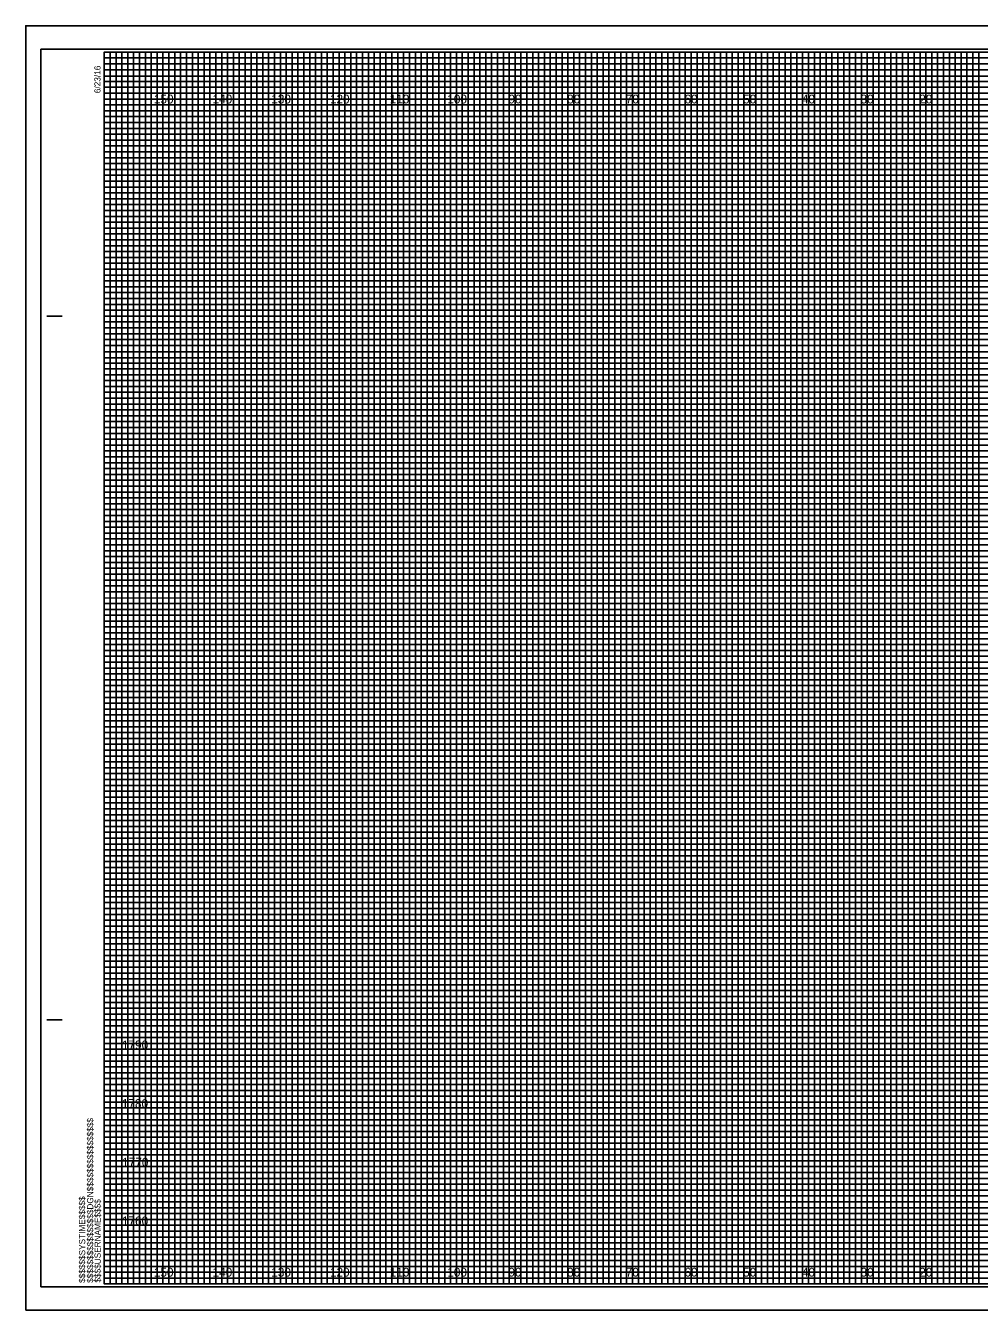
# Model space of a CAD drawing. Extents: x 791 to 1128, y -18 to 860.
# Drawn here: x 791.1 to 953.6, y 640.8 to 859.8 of the extents above; entities that cross this region are included whole.
import ezdxf

# ---------------------------------------------------------------- set-up
doc = ezdxf.new("R2010")
doc.units = 0
for name, color, linetype in [('Prop XS DDE', 7, 'Continuous'), ('Prop XS Earthwork Shape', 7, 'Continuous'), ('Raster_Level_0', 7, 'Continuous'), ('Scratch_Level_1', 7, 'Continuous'), ('Scratch_Level_3', 7, 'Continuous'), ('Sheet Cross Section CELL', 7, 'Continuous'), ('Sheet Cross Section Grid Minor 2 CELL', 7, 'Continuous'), ('Sheet Cutting Line CELL', 7, 'Continuous'), ('Sheet DOT Grid CELL', 7, 'Continuous'), ('Sheet Plot Border Inside CELL', 7, 'Continuous'), ('Sheet Plot Border Outside CELL', 7, 'Continuous')]:
    doc.layers.add(name, color=color, linetype=linetype)

msp = doc.modelspace()

# ---------------------------------------------------------------- linework, layer by layer
at = {"layer": 'Prop XS DDE'}
for p, q in [((804.53, 854.25), (1064.53, 854.25)), ((1064.53, 853.23), (804.53, 853.23)), ((804.53, 853.23), (804.53, 852.25)), ((804.53, 852.25), (1064.53, 852.25)), ((1064.53, 851.14), (804.53, 851.14)), ((804.53, 851.14), (804.53, 849.25)), ((804.53, 849.25), (1124.53, 849.25))]:
    msp.add_line(p, q, dxfattribs=at)
for points in [[(804.53, 848.25), (1074.53, 848.25), (1124.53, 848.25), (1124.53, 847.25), (804.53, 847.25)], [(804.53, 846.25), (1124.53, 846.25), (1124.53, 844.25), (804.53, 844.25)], [(804.53, 843.25), (1124.53, 843.25), (1124.53, 842.25), (804.53, 842.23)], [(804.53, 841.25), (1124.53, 841.25), (1124.53, 839.25), (804.53, 839.25)], [(804.53, 838.25), (1124.53, 838.25), (1124.53, 837.25), (804.53, 837.25)], [(804.53, 836.25), (1124.53, 836.25), (1124.53, 834.25), (804.53, 834.25)], [(804.53, 833.25), (1124.53, 833.25), (1124.53, 832.25), (804.53, 832.25)], [(804.53, 831.25), (1124.53, 831.25), (1124.53, 829.25), (804.53, 829.25)], [(804.53, 828.25), (1124.53, 828.25), (1124.53, 827.25), (804.53, 827.25)], [(804.53, 826.25), (1124.53, 826.25), (1124.53, 824.25), (804.53, 824.25)], [(804.53, 823.25), (1124.53, 823.25), (1124.53, 822.25), (804.53, 822.25)], [(804.53, 821.25), (1124.53, 821.25), (1124.53, 819.2), (1124.53, 818.25), (1124.53, 817.25), (804.53, 817.25)], [(804.53, 819.25), (1124.53, 819.25), (1124.53, 818.25), (804.53, 818.25)], [(804.53, 816.25), (1124.53, 816.25), (1124.53, 814.25), (804.53, 814.28)], [(804.53, 814.28), (1124.53, 814.25), (1124.53, 813.25), (804.53, 813.25)], [(804.53, 812.25), (1124.53, 812.25), (1124.53, 811.25), (804.53, 811.25)], [(804.53, 809.25), (1124.53, 809.25), (1124.53, 808.25), (804.53, 808.25)], [(804.53, 807.25), (1124.53, 807.25), (1124.53, 806.25), (804.53, 806.25)], [(804.46, 804.14), (1124.53, 804.14), (1124.53, 803.13), (804.46, 803.13)], [(804.53, 802.25), (1124.53, 802.25), (1124.53, 801.25), (804.53, 801.25)], [(804.53, 799.25), (1124.53, 799.25), (1124.53, 798.25), (804.53, 798.25)], [(804.53, 797.25), (1124.53, 797.25), (1124.53, 796.25), (804.53, 796.25)], [(804.53, 794.25), (1124.53, 794.25), (1124.53, 793.25), (804.53, 793.25)], [(804.53, 792.25), (1124.53, 792.25), (1124.53, 791.25), (804.53, 791.25)], [(804.53, 789.25), (1124.53, 789.25), (1124.53, 788.25), (804.53, 788.25)], [(804.53, 787.25), (1124.53, 787.25), (1124.53, 786.25), (804.53, 786.25)], [(804.53, 784.25), (1124.53, 784.25), (1124.52, 783.23), (804.53, 783.25)], [(804.53, 782.25), (1124.53, 782.25), (1124.53, 781.25), (804.53, 781.25)], [(804.53, 779.25), (1124.53, 779.25), (1124.53, 778.25), (804.53, 778.25)], [(804.53, 777.25), (1124.53, 777.25), (1124.53, 776.25), (804.53, 776.25)], [(804.53, 774.25), (1124.53, 774.25), (1124.53, 773.25), (804.53, 773.25)], [(804.53, 772.25), (1124.53, 772.25), (1124.53, 771.25), (804.53, 771.25)], [(804.53, 769.25), (1124.53, 769.25), (1124.53, 768.25), (804.53, 768.25)], [(804.53, 767.25), (1124.53, 767.25), (1124.53, 766.25), (804.53, 766.25)], [(804.53, 764.25), (1124.53, 764.25), (1124.53, 763.25), (804.53, 763.25)], [(804.53, 762.24), (1124.6, 762.16), (1124.53, 761.25), (804.53, 761.25)], [(804.53, 759.25), (1124.53, 759.25), (1124.53, 758.25), (804.53, 758.25)], [(804.53, 757.25), (1124.53, 757.25), (1124.53, 756.25), (804.53, 756.25)], [(804.53, 754.25), (1124.53, 754.25), (1124.53, 753.25), (804.53, 753.25)], [(804.53, 752.25), (1124.53, 752.25), (1124.53, 751.25), (804.53, 751.25)], [(804.53, 749.25), (1124.53, 749.25), (1124.53, 748.25), (804.53, 748.25)], [(804.53, 747.25), (1124.53, 747.25), (1124.53, 746.25), (804.53, 746.25)], [(804.53, 744.25), (1124.53, 744.25), (1124.53, 743.25), (804.53, 743.25)], [(804.53, 742.25), (1124.53, 742.25), (1124.53, 741.25), (804.53, 741.25)], [(804.53, 739.25), (1124.53, 739.25), (1124.53, 738.25), (804.53, 738.25)], [(804.53, 737.25), (1124.53, 737.25), (1124.53, 736.25), (804.53, 736.25)], [(804.53, 734.25), (1124.53, 734.25), (1124.53, 733.25), (804.53, 733.25)], [(804.53, 732.25), (1124.53, 732.25), (1124.53, 731.25), (804.53, 731.25)], [(804.53, 729.25), (1124.53, 729.25), (1124.53, 728.25), (804.53, 728.25)], [(804.53, 727.25), (1124.53, 727.25), (1124.53, 726.25), (804.53, 726.25)], [(804.53, 724.25), (1124.53, 724.25), (1124.52, 723.23), (804.53, 723.25)], [(804.53, 722.25), (1124.53, 722.25), (1124.53, 721.25), (804.53, 721.25)], [(804.53, 719.25), (1124.53, 719.25), (1124.53, 718.25), (804.53, 718.25)], [(804.53, 717.25), (1124.53, 717.25), (1124.53, 716.25), (804.53, 716.25)], [(804.53, 714.25), (1124.53, 714.25), (1124.53, 713.25), (804.53, 713.25)], [(804.53, 712.25), (1124.53, 712.25), (1124.53, 711.25), (804.53, 711.25)], [(804.53, 709.25), (1124.53, 709.25), (1124.53, 708.25), (804.53, 708.25)], [(804.53, 707.25), (1124.53, 707.25), (1124.53, 706.25), (804.53, 706.25)], [(804.53, 704.25), (1124.53, 704.25), (1124.53, 703.25), (804.53, 703.25)], [(804.53, 702.24), (1124.6, 702.16), (1124.53, 701.25), (804.53, 701.25)], [(804.53, 699.25), (1124.53, 699.25), (1124.53, 698.25), (804.53, 698.25)], [(804.53, 697.25), (1124.53, 697.25), (1124.53, 696.25), (804.53, 696.25)], [(804.53, 694.25), (1124.53, 694.25), (1124.53, 693.25), (804.53, 693.25)], [(804.53, 692.25), (1124.53, 692.25), (1124.53, 691.25), (804.53, 691.25)], [(804.53, 689.25), (1124.53, 689.25), (1124.53, 688.25), (804.53, 688.25)], [(804.53, 687.25), (1124.53, 687.25), (1124.53, 686.25), (804.53, 686.25)], [(804.53, 684.25), (1124.53, 684.25), (1124.53, 683.25), (804.53, 683.25)], [(804.53, 682.25), (1124.53, 682.25), (1124.53, 681.25), (804.53, 681.25)], [(804.53, 679.25), (1124.53, 679.25), (1124.53, 678.25), (804.53, 678.25)], [(804.53, 677.25), (1124.53, 677.25), (1124.53, 676.25), (804.53, 676.25)], [(804.53, 674.25), (1124.53, 674.25), (1124.53, 673.25), (804.53, 673.25)], [(804.53, 672.25), (1124.53, 672.25), (1124.53, 671.25), (804.53, 671.25)], [(804.53, 669.25), (1124.53, 669.25), (1124.53, 668.25), (804.53, 668.25)], [(804.53, 667.25), (1124.53, 667.25), (1124.53, 666.25), (804.53, 666.25)], [(804.53, 664.25), (1124.53, 664.25), (1124.53, 663.25), (804.53, 663.25)], [(804.53, 662.25), (1124.53, 662.25), (1124.53, 661.25), (804.53, 661.25)], [(804.53, 659.25), (1124.53, 659.25), (1124.53, 658.25), (804.53, 658.25)], [(804.53, 657.25), (1124.53, 657.25), (1124.53, 656.25), (804.53, 656.25)], [(804.53, 654.25), (1124.53, 654.25), (1124.53, 653.25), (804.53, 653.25)], [(804.53, 652.25), (1124.53, 652.25), (1124.53, 651.25), (804.53, 651.25)], [(804.53, 649.25), (1124.53, 649.25), (1124.53, 648.25), (804.53, 648.25)], [(804.53, 647.25), (1124.53, 647.25), (1124.53, 646.25), (804.53, 646.25)]]:
    msp.add_lwpolyline(points, dxfattribs=at)
at = {"layer": 'Prop XS Earthwork Shape'}
for points in [[(804.53, 855.25), (809.53, 855.25), (809.53, 645.25), (819.53, 645.25), (819.53, 855.25), (829.53, 855.25), (829.53, 645.25), (839.53, 645.25), (839.53, 855.25), (849.53, 855.25), (849.53, 645.25), (859.53, 645.25), (859.53, 855.25), (869.53, 855.25), (869.53, 645.25), (879.53, 645.25), (879.53, 855.25), (889.53, 855.25), (889.53, 645.25), (899.53, 645.25), (899.53, 855.25), (909.53, 855.25), (909.53, 645.25), (919.53, 645.25), (919.53, 855.25), (929.53, 855.25), (929.53, 645.25), (939.53, 645.25), (939.53, 855.25), (949.53, 855.25), (949.53, 645.25), (959.53, 645.25)], [(804.53, 850.25), (1079.53, 850.25)], [(804.53, 830.25), (1124.53, 830.25), (1124.53, 840.25), (804.53, 840.25)], [(804.53, 810.25), (1124.53, 810.25), (1124.53, 820.25), (804.53, 820.25)], [(804.53, 790.25), (1124.53, 790.25), (1124.53, 800.25), (804.53, 800.25)], [(804.53, 770.25), (1124.53, 770.25), (1124.53, 780.25), (804.53, 780.25)], [(804.53, 750.25), (1124.53, 750.25), (1124.53, 760.25), (804.53, 760.25)], [(804.53, 730.25), (1124.53, 730.25), (1124.53, 740.25), (804.53, 740.25)], [(804.53, 710.25), (1124.53, 710.25), (1124.53, 720.25), (804.53, 720.25)], [(804.53, 690.25), (1124.53, 690.25), (1124.53, 700.25), (804.53, 700.25)], [(804.53, 670.25), (1124.53, 670.25), (1124.53, 680.25), (804.53, 680.25)], [(804.53, 650.25), (1124.53, 650.25), (1124.53, 660.25), (804.53, 660.25)]]:
    msp.add_lwpolyline(points, dxfattribs=at)
at = {"layer": 'Scratch_Level_1'}
for p, q in [((814.53, 855.25), (804.53, 855.25)), ((814.53, 645.25), (814.53, 855.25)), ((834.53, 855.25), (824.53, 855.25)), ((824.53, 855.25), (824.53, 645.25)), ((834.53, 645.25), (834.53, 855.25)), ((854.53, 855.25), (844.53, 855.25)), ((844.53, 855.25), (844.53, 645.25)), ((854.53, 645.25), (854.53, 855.25)), ((874.53, 855.25), (864.53, 855.25)), ((864.53, 855.25), (864.53, 645.25)), ((874.53, 645.25), (874.53, 855.25)), ((894.53, 855.25), (884.53, 855.25)), ((884.53, 855.25), (884.53, 645.25)), ((894.53, 645.25), (894.53, 855.25)), ((914.53, 855.25), (904.53, 855.25)), ((904.53, 855.25), (904.53, 645.25)), ((914.53, 645.25), (914.53, 855.25)), ((934.53, 855.25), (924.53, 855.25)), ((924.53, 855.25), (924.53, 645.25)), ((934.53, 645.25), (934.53, 855.25)), ((954.53, 855.25), (944.53, 855.25)), ((944.53, 855.25), (944.53, 645.25)), ((824.53, 645.25), (814.53, 645.25)), ((844.53, 645.25), (834.53, 645.25)), ((864.53, 645.25), (854.53, 645.25)), ((884.53, 645.25), (874.53, 645.25)), ((904.53, 645.25), (894.53, 645.25)), ((924.53, 645.25), (914.53, 645.25)), ((944.53, 645.25), (934.53, 645.25))]:
    msp.add_line(p, q, dxfattribs=at)
for points in [[(804.53, 845.25), (1124.53, 845.25), (1124.53, 835.25), (804.53, 835.25)], [(804.53, 825.25), (1124.53, 825.25), (1124.53, 815.25), (804.53, 815.25)], [(804.53, 805.25), (1124.53, 805.25), (1124.53, 795.25), (804.53, 795.25)], [(804.53, 785.25), (1124.53, 785.25), (1124.53, 775.25), (804.53, 775.25)], [(804.53, 765.25), (1124.53, 765.25), (1124.53, 755.25), (804.53, 755.25)], [(804.53, 745.25), (1124.53, 745.25), (1124.53, 735.25), (804.53, 735.25)], [(804.53, 725.25), (1124.53, 725.25), (1124.53, 715.25), (804.53, 715.25)], [(804.53, 705.25), (1124.53, 705.25), (1124.53, 695.25), (804.53, 695.25)], [(804.53, 685.25), (1124.53, 685.25), (1124.53, 675.25), (804.53, 675.25)], [(804.53, 665.25), (1124.53, 665.25), (1124.53, 655.25), (804.53, 655.25)]]:
    msp.add_lwpolyline(points, dxfattribs=at)
at = {"layer": 'Sheet Cross Section CELL'}
for p, q in [((794.73, 810.25), (797.23, 810.25)), ((794.83, 810.25), (797.33, 810.25)), ((794.73, 690.25), (797.23, 690.25)), ((794.83, 690.25), (797.33, 690.25)), ((804.53, 645.25), (804.53, 645.25)), ((804.53, 645.25), (804.53, 645.25)), ((804.53, 645.25), (804.53, 645.25)), ((804.53, 645.25), (804.53, 645.25)), ((804.53, 645.25), (804.53, 645.25)), ((804.53, 645.25), (804.53, 645.25)), ((804.53, 645.25), (804.53, 645.25))]:
    msp.add_line(p, q, dxfattribs=at)
msp.add_lwpolyline([(1124.53, 855.25), (804.53, 855.25), (804.53, 645.25), (1124.53, 645.25)], close=True, dxfattribs=at)
at = {"layer": 'Sheet Cross Section Grid Minor 2 CELL'}
for points in [[(804.53, 645.25), (805.53, 645.25), (805.53, 855.25), (806.53, 855.25), (806.53, 645.25)], [(806.53, 645.25), (807.53, 645.25), (807.53, 855.25), (808.53, 855.25), (808.53, 645.25)], [(809.53, 645.25), (810.53, 645.25), (810.53, 855.25), (811.53, 855.25), (811.53, 645.25)], [(811.53, 645.25), (812.53, 645.25), (812.53, 855.25), (813.53, 855.25), (813.53, 645.25)], [(814.53, 645.25), (815.53, 645.25), (815.53, 855.25), (816.53, 855.25), (816.53, 645.25)], [(816.53, 645.25), (817.53, 645.25), (817.53, 855.25), (818.53, 855.25), (818.53, 645.25)], [(819.53, 645.25), (820.53, 645.25), (820.53, 855.25), (821.53, 855.25), (821.53, 645.25)], [(821.53, 645.25), (822.53, 645.25), (822.53, 855.25), (823.53, 855.25), (823.53, 645.25)], [(824.53, 645.25), (825.53, 645.25), (825.53, 855.25), (826.53, 855.25), (826.53, 645.25)], [(826.53, 645.25), (827.53, 645.25), (827.53, 855.25), (828.53, 855.25), (828.53, 645.25)], [(829.53, 645.25), (830.53, 645.25), (830.53, 855.25), (831.53, 855.25), (831.53, 645.25)], [(831.53, 645.25), (832.53, 645.25), (832.53, 855.25), (833.53, 855.25), (833.53, 645.25)], [(834.53, 645.25), (835.53, 645.25), (835.53, 855.25), (836.53, 855.25), (836.53, 645.25)], [(836.53, 645.25), (837.53, 645.25), (837.53, 855.25), (838.53, 855.25), (838.53, 645.25)], [(839.53, 645.25), (840.53, 645.25), (840.53, 855.25), (841.53, 855.25), (841.53, 645.25)], [(841.53, 645.25), (842.53, 645.25), (842.53, 855.25), (843.53, 855.25), (843.53, 645.25)], [(844.53, 645.25), (845.53, 645.25), (845.53, 855.25), (846.53, 855.25), (846.53, 645.25)], [(846.53, 645.25), (847.53, 645.25), (847.53, 855.25), (848.53, 855.25), (848.53, 645.25)], [(849.53, 645.25), (850.53, 645.25), (850.53, 855.25), (851.53, 855.25), (851.53, 645.25)], [(851.53, 645.25), (852.53, 645.25), (852.53, 855.25), (853.53, 855.25), (853.53, 645.25)], [(854.53, 645.25), (855.53, 645.25), (855.53, 855.25), (856.53, 855.25), (856.53, 645.25)], [(856.53, 645.25), (857.53, 645.25), (857.53, 855.25), (858.53, 855.25), (858.53, 645.25)], [(859.53, 645.25), (860.53, 645.25), (860.53, 855.25), (861.53, 855.25), (861.53, 645.25)], [(861.53, 645.25), (862.53, 645.25), (862.53, 855.25), (863.53, 855.25), (863.53, 645.25)], [(864.53, 645.25), (865.53, 645.25), (865.53, 855.25), (866.53, 855.25), (866.53, 645.25)], [(866.53, 645.25), (867.53, 645.25), (867.53, 855.25), (868.53, 855.25), (868.53, 645.25)], [(869.53, 645.25), (870.53, 645.25), (870.53, 855.25), (871.53, 855.25), (871.53, 645.25)], [(871.53, 645.25), (872.53, 645.25), (872.53, 855.25), (873.53, 855.25), (873.53, 645.25)], [(874.53, 645.25), (875.53, 645.25), (875.53, 855.25), (876.53, 855.25), (876.53, 645.25)], [(876.53, 645.25), (877.53, 645.25), (877.53, 855.25), (878.53, 855.25), (878.53, 645.25)], [(879.53, 645.25), (880.53, 645.25), (880.53, 855.25), (881.53, 855.25), (881.53, 645.25)], [(881.53, 645.25), (882.53, 645.25), (882.53, 855.25), (883.53, 855.25), (883.53, 645.25)], [(884.53, 645.25), (885.53, 645.25), (885.53, 855.25), (886.53, 855.25), (886.53, 645.25)], [(886.53, 645.25), (887.53, 645.25), (887.53, 855.25), (888.53, 855.25), (888.53, 645.25)], [(889.53, 645.25), (890.53, 645.25), (890.53, 855.25), (891.53, 855.25), (891.53, 645.25)], [(891.53, 645.25), (892.53, 645.25), (892.53, 855.25), (893.53, 855.25), (893.53, 645.25)], [(894.53, 645.25), (895.53, 645.25), (895.53, 855.25), (896.53, 855.25), (896.53, 645.25)], [(896.53, 645.25), (897.53, 645.25), (897.53, 855.25), (898.53, 855.25), (898.53, 645.25)], [(899.53, 645.25), (900.53, 645.25), (900.53, 855.25), (901.53, 855.25), (901.53, 645.25)], [(901.53, 645.25), (902.53, 645.25), (902.53, 855.25), (903.53, 855.25), (903.53, 645.25)], [(904.53, 645.25), (905.53, 645.25), (905.53, 855.25), (906.53, 855.25), (906.53, 645.25)], [(906.53, 645.25), (907.53, 645.25), (907.53, 855.25), (908.53, 855.25), (908.53, 645.25)], [(909.53, 645.25), (910.53, 645.25), (910.53, 855.25), (911.53, 855.25), (911.53, 645.25)], [(911.53, 645.25), (912.53, 645.25), (912.53, 855.25), (913.53, 855.25), (913.53, 645.25)], [(914.53, 645.25), (915.53, 645.25), (915.53, 855.25), (916.53, 855.25), (916.53, 645.25)], [(916.53, 645.25), (917.53, 645.25), (917.53, 855.25), (918.53, 855.25), (918.53, 645.25)], [(919.53, 645.25), (920.53, 645.25), (920.53, 855.25), (921.53, 855.25), (921.53, 645.25)], [(921.53, 645.25), (922.53, 645.25), (922.53, 855.25), (923.53, 855.25), (923.53, 645.25)], [(924.53, 645.25), (925.53, 645.25), (925.53, 855.25), (926.53, 855.25), (926.53, 645.25)], [(926.53, 645.25), (927.53, 645.25), (927.53, 855.25), (928.53, 855.25), (928.53, 645.25)], [(929.53, 645.25), (930.53, 645.25), (930.53, 855.25), (931.53, 855.25), (931.53, 645.25)], [(931.53, 645.25), (932.53, 645.25), (932.53, 855.25), (933.53, 855.25), (933.53, 645.25)], [(934.53, 645.25), (935.53, 645.25), (935.53, 855.25), (936.53, 855.25), (936.53, 645.25)], [(936.53, 645.25), (937.53, 645.25), (937.53, 855.25), (938.53, 855.25), (938.53, 645.25)], [(939.53, 645.25), (940.53, 645.25), (940.53, 855.25), (941.53, 855.25), (941.53, 645.25)], [(941.53, 645.25), (942.53, 645.25), (942.53, 855.25), (943.53, 855.25), (943.53, 645.25)], [(944.53, 645.25), (945.53, 645.25), (945.53, 855.25), (946.53, 855.25), (946.53, 645.25)], [(946.53, 645.25), (947.53, 645.25), (947.53, 855.25), (948.53, 855.25), (948.53, 645.25)], [(949.53, 645.25), (950.53, 645.25), (950.53, 855.25), (951.53, 855.25), (951.53, 645.25)], [(951.53, 645.25), (952.53, 645.25), (952.53, 855.25), (953.53, 855.25), (953.53, 645.25)]]:
    msp.add_lwpolyline(points, dxfattribs=at)
at = {"layer": 'Sheet Cutting Line CELL'}
for p, q in [((1127.83, 859.75), (791.13, 859.75)), ((791.13, 859.75), (791.13, 640.75)), ((791.13, 640.75), (1127.83, 640.75))]:
    msp.add_line(p, q, dxfattribs=at)
at = {"layer": 'Sheet DOT Grid CELL'}
for p, q in [((814.53, 645.25), (814.53, 855.25)), ((824.53, 645.25), (824.53, 855.25)), ((834.53, 645.25), (834.53, 855.25)), ((844.53, 645.25), (844.53, 855.25)), ((854.53, 645.25), (854.53, 855.25)), ((864.53, 645.25), (864.53, 855.25)), ((874.53, 645.25), (874.53, 855.25)), ((884.53, 645.25), (884.53, 855.25)), ((894.53, 645.25), (894.53, 855.25)), ((904.53, 645.25), (904.53, 855.25)), ((914.53, 645.25), (914.53, 855.25)), ((924.53, 645.25), (924.53, 855.25)), ((934.53, 645.25), (934.53, 855.25)), ((944.53, 645.25), (944.53, 855.25)), ((804.53, 845.25), (1124.53, 845.25)), ((804.53, 835.25), (1124.53, 835.25)), ((804.53, 825.25), (1124.53, 825.25)), ((804.53, 815.25), (1124.53, 815.25)), ((804.53, 805.25), (1124.53, 805.25)), ((804.53, 795.25), (1124.53, 795.25)), ((804.53, 785.25), (1124.53, 785.25)), ((804.53, 775.25), (1124.53, 775.25)), ((804.53, 765.25), (1124.53, 765.25)), ((804.53, 755.25), (1124.53, 755.25)), ((804.53, 745.25), (1124.53, 745.25)), ((804.53, 735.25), (1124.53, 735.25)), ((804.53, 725.25), (1124.53, 725.25)), ((804.53, 715.25), (1124.53, 715.25)), ((804.53, 705.25), (1124.53, 705.25)), ((804.53, 695.25), (1124.53, 695.25)), ((804.53, 685.25), (1124.53, 685.25)), ((804.53, 675.25), (1124.53, 675.25)), ((804.53, 665.25), (1124.53, 665.25)), ((804.53, 655.25), (1124.53, 655.25))]:
    msp.add_line(p, q, dxfattribs=at)
at = {"layer": 'Sheet Plot Border Inside CELL'}
msp.add_lwpolyline([(793.73, 644.75), (1126.93, 644.75), (1126.93, 855.75), (793.73, 855.75)], close=True, dxfattribs=at)
at = {"layer": 'Sheet Plot Border Outside CELL'}
msp.add_lwpolyline([(791.13, 640.75), (1127.83, 640.75), (1127.83, 859.75), (791.13, 859.75)], close=True, dxfattribs=at)

# ---------------------------------------------------------------- texts
at = {"layer": 'Raster_Level_0'}
for s, p in [('150', (812.98, 846.5)), ('140', (822.98, 846.5)), ('130', (832.98, 846.5)), ('120', (842.98, 846.5)), ('110', (853.16, 846.5)), ('100', (862.98, 846.5)), ('90', (873.39, 846.5)), ('80', (883.39, 846.5)), ('70', (893.39, 846.5)), ('60', (903.39, 846.5)), ('50', (913.39, 846.5)), ('40', (923.39, 846.5)), ('30', (933.39, 846.5)), ('20', (943.39, 846.5)), ('150', (812.98, 646.5)), ('140', (822.98, 646.5)), ('130', (832.98, 646.5)), ('120', (842.98, 646.5)), ('110', (853.16, 646.5)), ('100', (862.98, 646.5)), ('90', (873.39, 646.5)), ('80', (883.39, 646.5)), ('70', (893.39, 646.5)), ('60', (903.39, 646.5)), ('50', (913.39, 646.5)), ('40', (923.39, 646.5)), ('30', (933.39, 646.5)), ('20', (943.39, 646.5))]:
    msp.add_text(s, height=1.5, dxfattribs=at).set_placement(p)
at = {"layer": 'Scratch_Level_3'}
for s, p in [('1790', (807.54, 685.25)), ('1780', (807.52, 675.25)), ('1770', (807.57, 665.25)), ('1760', (807.54, 655.25))]:
    msp.add_text(s, height=1.5, dxfattribs=at).set_placement(p)
at = {"layer": 'Sheet Cross Section CELL'}
for s, p in [('6/23/16', (803.88, 848.25)), ('$$$$$$$$$$$$$$$$DGN$$$$$$$$$$$$$$$$', (802.65, 645.43)), ('$$$$$$SYSTIME$$$$$', (801.27, 645.43)), ('$$$$USERNAME$$$$', (803.91, 645.48))]:
    msp.add_text(s, height=1.05, rotation=90, dxfattribs=at).set_placement(p)

doc.saveas('drawing.dxf')
